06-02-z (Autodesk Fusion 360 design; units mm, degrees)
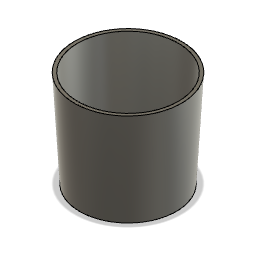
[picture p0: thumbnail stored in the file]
sketch "スケッチ" plane through (0, 0, 0) normal (0, 0, 1) x axis (1, 0, 0)
  line L1 (0, 45) -> (0, 0)
  line L2 (-25, 45) -> (0, 45)
  line L3 (-22.5, 0) -> (-25, 45)
  line L4 (0, 0) -> (-22.5, 0)
  point P1 (0, 0)
  point P2 (0, 0)
  point P3 (0, 45)
  point P5 (-22.5, 0)
  coincident P1 P2
  vertical L1
  perpendicular L1 L2
  perpendicular L1 L4
  dimension "d1" = 50
  dimension "d2" distance P2 P3 = 45
  dimension "d3" distance L1 P5 = 45
revolve "回転" sketch "スケッチ" AlongAngle 360
shell "シェル" innerThickness 1.5
offset_faces "面をオフセット" distance 1.5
